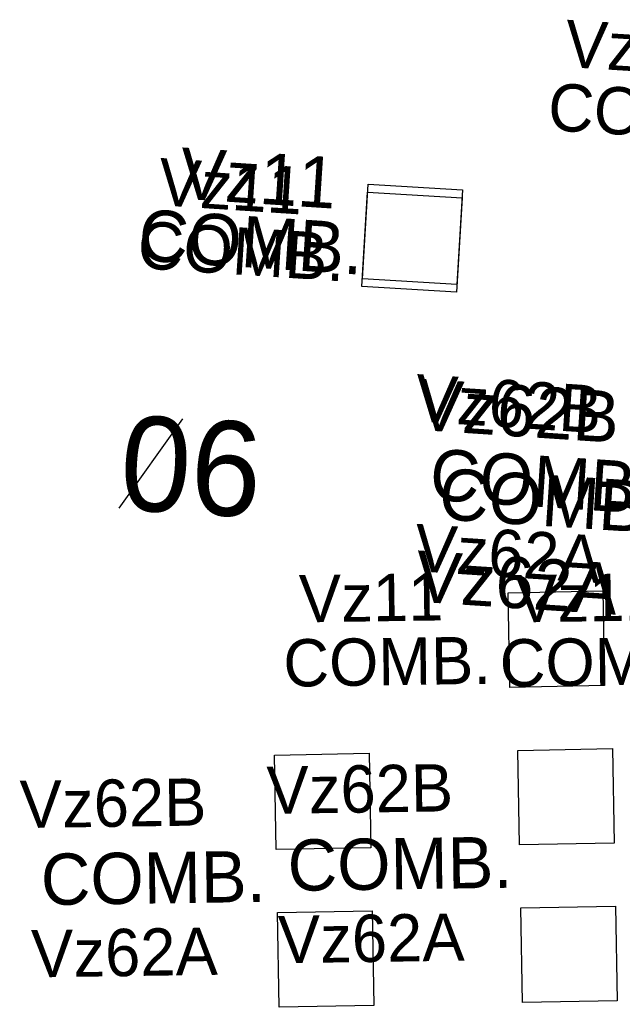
# Model space of a CAD drawing. Extents: x 647787 to 668496, y 640478 to 654412.
# Drawn here: x 662563.9 to 662602, y 647224.1 to 647286.7 of the extents above; entities that cross this region are included whole.
import ezdxf

# ---------------------------------------------------------------- set-up
doc = ezdxf.new("R2010")
doc.units = 0
for name, color, linetype in [('Default', 7, 'Continuous'), ('TEMP_DETECTION ZONE_Stage 2', 7, 'Continuous'), ('TEMP_DETECTION ZONE_STAGE 3', 7, 'Continuous'), ('TEMP_DETECTION_ZONE_STAGE 4', 7, 'Continuous'), ('TEMP_DETECTION_ZONE_STAGE 5', 7, 'Continuous'), ('TEMP_SIGNAL_POLES_STAGE 1B', 7, 'Continuous')]:
    doc.layers.add(name, color=color, linetype=linetype)

msp = doc.modelspace()

# ---------------------------------------------------------------- linework, layer by layer
at = {"layer": 'Default'}
msp.add_line((662570.151, 647255.743), (662574.191, 647261.4), dxfattribs=at)
msp.add_line((662570.151, 647255.743), (662574.191, 647261.4), dxfattribs=at)
at = {"layer": 'TEMP_DETECTION ZONE_STAGE 3'}
for points in [[(662601.532, 647234.493), (662595.534, 647234.377), (662595.418, 647240.376), (662601.417, 647240.492)], [(662601.725, 647224.495), (662595.726, 647224.379), (662595.61, 647230.378), (662601.609, 647230.494)]]:
    msp.add_lwpolyline(points, close=True, dxfattribs=at)
at = {"layer": 'TEMP_DETECTION_ZONE_STAGE 4'}
for points in [[(662600.914, 647244.483), (662594.916, 647244.367), (662594.8, 647250.366), (662600.799, 647250.482)], [(662586.109, 647234.196), (662580.111, 647234.081), (662579.995, 647240.08), (662585.994, 647240.195)], [(662586.302, 647224.198), (662580.303, 647224.083), (662580.187, 647230.082), (662586.186, 647230.197)]]:
    msp.add_lwpolyline(points, close=True, dxfattribs=at)
at = {"layer": 'TEMP_DETECTION_ZONE_STAGE 5'}
msp.add_lwpolyline([(662591.528, 647269.425), (662585.539, 647269.787), (662585.9, 647275.776), (662591.889, 647275.415)], close=True, dxfattribs=at)
at = {"layer": 'TEMP_SIGNAL_POLES_STAGE 1B'}
msp.add_lwpolyline([(662591.558, 647269.925), (662585.569, 647270.286), (662585.93, 647276.275), (662591.92, 647275.914)], close=True, dxfattribs=at)

# ---------------------------------------------------------------- texts
at = {"layer": 'Default'}
msp.add_text('06', height=6, rotation=356.63656, dxfattribs=at).set_placement((662570.086, 647255.659))
msp.add_text('06', height=6, rotation=356.63656, dxfattribs=at).set_placement((662570.086, 647255.659))
at = {"layer": 'TEMP_DETECTION ZONE_Stage 2'}
for s, p in [('Vz13', (662598.346, 647283.717)), ('COMB.', (662597.269, 647279.711))]:
    msp.add_text(s, height=3, rotation=356.52674, dxfattribs=at).set_placement(p)
at = {"layer": 'TEMP_DETECTION ZONE_STAGE 3'}
for s, height, rotation, p in [('Vz11', 3, 0.832, (662595.286, 647248.486)), ('COMB.', 3, 0.832, (662594.294, 647244.408)), ('Vz62B', 3, 0.81961, (662579.52, 647236.344)), ('COMB.', 3.25, 0.81961, (662580.855, 647231.46)), ('Vz62A', 3, 0.81961, (662580.24, 647226.871))]:
    msp.add_text(s, height=height, rotation=rotation, dxfattribs=at).set_placement(p)
at = {"layer": 'TEMP_DETECTION_ZONE_STAGE 4'}
for s, height, rotation, p in [('Vz11', 3, 0.832, (662581.574, 647248.486)), ('COMB.', 3, 0.832, (662580.582, 647244.408)), ('Vz62B', 3, 0.81961, (662563.881, 647235.444)), ('COMB.', 3.25, 0.81961, (662565.216, 647230.561)), ('Vz62A', 3, 0.81961, (662564.601, 647225.972))]:
    msp.add_text(s, height=height, rotation=rotation, dxfattribs=at).set_placement(p)
at = {"layer": 'TEMP_DETECTION_ZONE_STAGE 5'}
for s, height, rotation, p in [('Vz11', 3, 356.2758, (662572.567, 647274.953)), ('COMB.', 3, 356.2758, (662571.254, 647270.966)), ('Vz62B', 3, 356.2634, (662588.83, 647261.248)), ('COMB.', 3.25, 356.2634, (662589.773, 647256.274)), ('Vz62A', 3, 356.2634, (662588.795, 647251.749))]:
    msp.add_text(s, height=height, rotation=rotation, dxfattribs=at).set_placement(p)
at = {"layer": 'TEMP_SIGNAL_POLES_STAGE 1B'}
for s, rotation, p in [('Vz11', 356.2758, (662573.92, 647275.371)), ('COMB.', 356.2758, (662571.307, 647271.463)), ('Vz62B', 356.2634, (662588.959, 647260.705)), ('COMB.', 356.2634, (662590.351, 647255.044)), ('Vz62A', 356.2634, (662588.859, 647249.812))]:
    msp.add_text(s, height=3.25, rotation=rotation, dxfattribs=at).set_placement(p)

doc.saveas('drawing.dxf')
